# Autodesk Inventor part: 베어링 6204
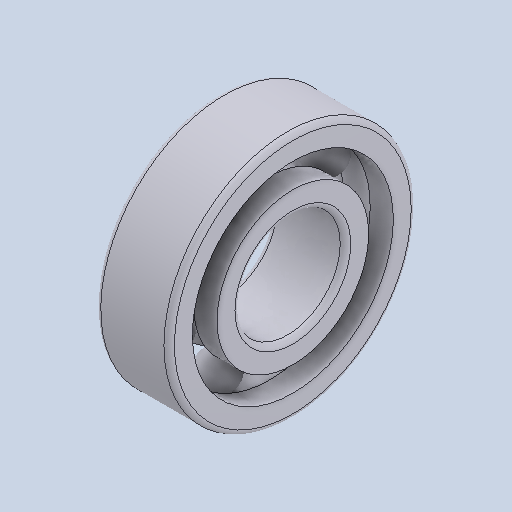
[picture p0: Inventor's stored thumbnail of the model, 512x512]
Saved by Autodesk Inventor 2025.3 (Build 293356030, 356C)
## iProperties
Created: 2025-08
Part Number: 베어링 6204
Material: 강철, 연강
Description: 깊은 그루브 볼 베어링
Document SubType Name: Modeling
Designer: infra011
Density: 7.86 g/cm^3
Appearance: 기본값
Author: jhkim
Sending System: Autodesk Inventor 2026
Preprocessor: ST-DEVELOPER v20.1
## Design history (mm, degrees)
feature "Solid1"
feature "Solid1:1"
feature "Solid1:2"
feature "Solid1:3"
feature "Solid1:4"
feature "Solid1:5"
feature "Solid1:6"
feature "Solid1:7"
feature "Solid1:8"
node "솔리드1"
node "솔리드2"
node "솔리드3"
node "솔리드4"
node "솔리드5"
node "솔리드6"
node "솔리드7"
node "솔리드8"
node "솔리드9"
